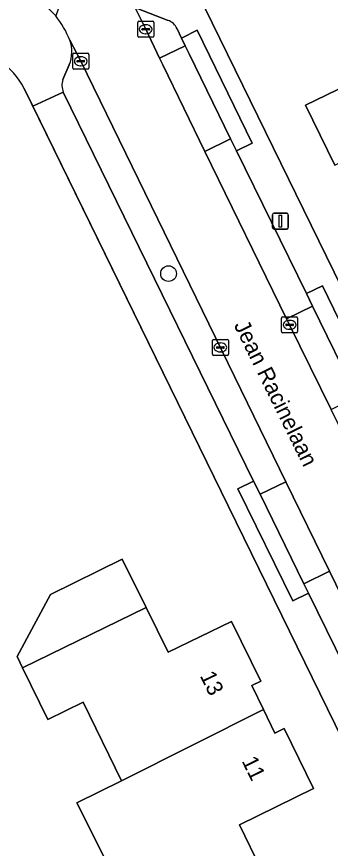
# Model space of a CAD drawing. Extents: x 160455 to 162082, y 388339 to 389736.
# Drawn here: x 160698.2 to 160717.8, y 388875.4 to 388927.4 of the extents above; entities that cross this region are included whole.
import ezdxf

# ---------------------------------------------------------------- set-up
doc = ezdxf.new("R2010")
doc.units = 0
for name, color, linetype in [('IMGEO_Boom', 7, 'Continuous'), ('IMGEO_Erf', 7, 'Continuous'), ('IMGEO_Kolk', 7, 'Continuous'), ('IMGEO_Lichtmast', 7, 'Continuous'), ('IMGEO_Muur', 7, 'Continuous'), ('IMGEO_Openbare_ruimte_label', 7, 'Continuous'), ('IMGEO_Pand', 7, 'Continuous'), ('IMGEO_Pand_nummerreeks', 7, 'Continuous'), ('IMGEO_Parkeervlak_open', 7, 'Continuous'), ('IMGEO_Rijbaan_lokaal_gesloten', 7, 'Continuous'), ('IMGEO_Rijbaan_lokaal_open', 7, 'Continuous'), ('IMGEO_Voetpad_open', 7, 'Continuous')]:
    doc.layers.add(name, color=color, linetype=linetype)

msp = doc.modelspace()

# ---------------------------------------------------------------- linework, layer by layer
at = {"layer": 'IMGEO_Boom'}
msp.add_circle((160707.652, 388911.311), 0.489, dxfattribs=at)
at = {"layer": 'IMGEO_Erf'}
for points in [[(160702.295, 388943.534), (160746.543, 388853.042), (160750.115, 388854.798), (160751.768, 388851.437), (160755.566, 388854.723), (160761.578, 388855.902), (160765.312, 388848.254), (160760.001, 388845.647), (160754.69, 388843.04), (160753.115, 388846.244), (160750.513, 388844.965), (160752.505, 388840.773)], [(160718.045, 388918.085), (160716.205, 388921.838), (160720.813, 388924.069)], [(160711.402, 388896.761), (160699.17, 388921.78), (160698.632, 388922.881)], [(160741.386, 388835.41), (160711.402, 388896.761)], [(160704.389, 388873.325), (160701.933, 388878.214), (160704.709, 388879.608), (160702.314, 388884.518), (160700.11, 388883.443), (160698.536, 388886.67), (160698.192, 388887.375), (160700.276, 388891.241), (160704.755, 388893.463), (160706.26, 388890.428), (160707.638, 388887.651), (160711.58, 388889.566), (160713.415, 388885.829), (160712.859, 388885.556), (160713.584, 388884.066), (160714.305, 388882.584), (160714.873, 388882.862), (160716.707, 388879.122), (160712.084, 388876.854), (160713.447, 388874.052)]]:
    msp.add_lwpolyline(points, dxfattribs=at)
msp.add_arc((160694.823, 388921.023), 4.238, 26.0033, 154.6119, dxfattribs=at)
at = {"layer": 'IMGEO_Kolk'}
for p, q in [((160705.728, 388926.167), (160705.728, 388927.019)), ((160705.803, 388927.093), (160706.655, 388927.093)), ((160706.216, 388926.873), (160706.241, 388926.873)), ((160706.729, 388927.019), (160706.729, 388926.167)), ((160705.987, 388926.587), (160705.987, 388926.599)), ((160706.425, 388926.55), (160706.027, 388926.55)), ((160706.03, 388926.636), (160706.428, 388926.636)), ((160706.239, 388926.313), (160706.214, 388926.313)), ((160706.471, 388926.599), (160706.471, 388926.587)), ((160706.655, 388926.093), (160705.803, 388926.093)), ((160701.669, 388924.168), (160701.669, 388925.02)), ((160701.744, 388925.094), (160702.596, 388925.094)), ((160701.971, 388924.637), (160702.369, 388924.637)), ((160702.157, 388924.874), (160702.182, 388924.874)), ((160702.67, 388925.02), (160702.67, 388924.168)), ((160701.928, 388924.588), (160701.928, 388924.6)), ((160702.366, 388924.551), (160701.968, 388924.551)), ((160702.18, 388924.314), (160702.155, 388924.314)), ((160702.412, 388924.6), (160702.412, 388924.588)), ((160702.596, 388924.094), (160701.744, 388924.094)), ((160714.72, 388907.685), (160714.72, 388908.537)), ((160714.795, 388908.611), (160715.647, 388908.611)), ((160715.721, 388908.537), (160715.721, 388907.685)), ((160714.979, 388908.105), (160714.979, 388908.117)), ((160715.417, 388908.068), (160715.019, 388908.068)), ((160715.022, 388908.154), (160715.42, 388908.154)), ((160715.208, 388908.391), (160715.233, 388908.391)), ((160715.463, 388908.117), (160715.463, 388908.105)), ((160715.647, 388907.611), (160714.795, 388907.611)), ((160715.231, 388907.831), (160715.206, 388907.831)), ((160710.393, 388906.269), (160710.393, 388907.121)), ((160710.468, 388907.195), (160711.32, 388907.195)), ((160710.881, 388906.975), (160710.906, 388906.975)), ((160711.394, 388907.121), (160711.394, 388906.269)), ((160710.652, 388906.689), (160710.652, 388906.701)), ((160711.09, 388906.652), (160710.692, 388906.652)), ((160710.695, 388906.738), (160711.093, 388906.738)), ((160711.136, 388906.701), (160711.136, 388906.689)), ((160711.32, 388906.195), (160710.468, 388906.195)), ((160710.904, 388906.415), (160710.879, 388906.415))]:
    msp.add_line(p, q, dxfattribs=at)
for points in [[(160705.728, 388926.167), (160705.728, 388927.019)], [(160705.803, 388927.093), (160706.655, 388927.093)], [(160706.729, 388927.019), (160706.729, 388926.167)], [(160706.655, 388926.093), (160705.803, 388926.093)], [(160701.669, 388924.168), (160701.669, 388925.02)], [(160701.744, 388925.094), (160702.596, 388925.094)], [(160702.67, 388925.02), (160702.67, 388924.168)], [(160702.596, 388924.094), (160701.744, 388924.094)], [(160714.72, 388907.685), (160714.72, 388908.537)], [(160714.795, 388908.611), (160715.647, 388908.611)], [(160715.721, 388908.537), (160715.721, 388907.685)], [(160715.647, 388907.611), (160714.795, 388907.611)], [(160710.393, 388906.269), (160710.393, 388907.121)], [(160710.468, 388907.195), (160711.32, 388907.195)], [(160711.394, 388907.121), (160711.394, 388906.269)], [(160711.32, 388906.195), (160710.468, 388906.195)]]:
    msp.add_lwpolyline(points, dxfattribs=at)
for centre, radius, start, end in [((160705.805, 388927.017), 0.0765, 91.552, 178.448), ((160705.805, 388927.017), 0.0765, 91.552, 178.448), ((160706.653, 388927.017), 0.0765, 1.552, 88.448), ((160706.653, 388927.017), 0.0765, 1.552, 88.448), ((160706.027, 388926.596), 0.0403, 85.8775, 175.7526), ((160706.024, 388926.586), 0.0366, 178.938, 274.7102), ((160706.428, 388926.593), 0.043, 264.8664, 352.4533), ((160706.432, 388926.598), 0.0386, 1.7309, 96.639), ((160705.805, 388926.169), 0.0765, 181.552, 268.448), ((160705.805, 388926.169), 0.0765, 181.552, 268.448), ((160706.653, 388926.169), 0.0765, 271.552, 358.448), ((160706.653, 388926.169), 0.0765, 271.552, 358.448), ((160701.746, 388925.018), 0.0765, 91.552, 178.448), ((160701.746, 388925.018), 0.0765, 91.552, 178.448), ((160701.968, 388924.597), 0.0403, 85.8775, 175.7526), ((160702.373, 388924.599), 0.0386, 1.7309, 96.639), ((160702.594, 388925.018), 0.0765, 1.552, 88.448), ((160702.594, 388925.018), 0.0765, 1.552, 88.448), ((160701.746, 388924.17), 0.0765, 181.552, 268.448), ((160701.746, 388924.17), 0.0765, 181.552, 268.448), ((160701.965, 388924.587), 0.0366, 178.938, 274.7102), ((160702.369, 388924.594), 0.043, 264.8664, 352.4533), ((160702.594, 388924.17), 0.0765, 271.552, 358.448), ((160702.594, 388924.17), 0.0765, 271.552, 358.448), ((160714.797, 388908.535), 0.0765, 91.552, 178.448), ((160714.797, 388908.535), 0.0765, 91.552, 178.448), ((160715.645, 388908.535), 0.0765, 1.552, 88.448), ((160715.645, 388908.535), 0.0765, 1.552, 88.448), ((160715.019, 388908.114), 0.0403, 85.8775, 175.7526), ((160715.016, 388908.104), 0.0366, 178.938, 274.7102), ((160715.42, 388908.111), 0.043, 264.8664, 352.4533), ((160715.424, 388908.116), 0.0386, 1.7309, 96.639), ((160714.797, 388907.687), 0.0765, 181.552, 268.448), ((160714.797, 388907.687), 0.0765, 181.552, 268.448), ((160715.645, 388907.687), 0.0765, 271.552, 358.448), ((160715.645, 388907.687), 0.0765, 271.552, 358.448), ((160710.47, 388907.119), 0.0765, 91.552, 178.448), ((160710.47, 388907.119), 0.0765, 91.552, 178.448), ((160711.318, 388907.119), 0.0765, 1.552, 88.448), ((160711.318, 388907.119), 0.0765, 1.552, 88.448), ((160710.692, 388906.698), 0.0403, 85.8775, 175.7526), ((160710.689, 388906.688), 0.0366, 178.938, 274.7102), ((160711.093, 388906.695), 0.043, 264.8664, 352.4533), ((160711.097, 388906.7), 0.0386, 1.7309, 96.639), ((160710.47, 388906.271), 0.0765, 181.552, 268.448), ((160710.47, 388906.271), 0.0765, 181.552, 268.448), ((160711.318, 388906.271), 0.0765, 271.552, 358.448), ((160711.318, 388906.271), 0.0765, 271.552, 358.448)]:
    msp.add_arc(centre, radius, start, end, dxfattribs=at)
for centre, major_axis, ratio, start_param, end_param in [((160706.215, 388926.593), (-0.387, 0.002), 0.722429, 4.712389, 7.853982), ((160706.24, 388926.593), (-0.39, 0.002), 0.717154, 1.570796, 4.712389), ((160702.156, 388924.594), (-0.387, 0.002), 0.722429, 4.712389, 7.853982), ((160702.181, 388924.594), (-0.39, 0.002), 0.717154, 1.570796, 4.712389), ((160715.207, 388908.111), (-0.387, 0.002), 0.722429, 4.712389, 7.853982), ((160715.232, 388908.111), (-0.39, 0.002), 0.717154, 1.570796, 4.712389), ((160710.88, 388906.695), (-0.387, 0.002), 0.722429, 4.712389, 7.853982), ((160710.905, 388906.695), (-0.39, 0.002), 0.717154, 1.570796, 4.712389)]:
    msp.add_ellipse(centre, major_axis=major_axis, ratio=ratio, start_param=start_param, end_param=end_param, dxfattribs=at)
at = {"layer": 'IMGEO_Lichtmast'}
for p, q in [((160714.148, 388914.196), (160714.148, 388914.996)), ((160714.148, 388914.996), (160714.148, 388914.196)), ((160714.248, 388915.096), (160715.038, 388915.096)), ((160715.038, 388915.096), (160714.248, 388915.096)), ((160715.138, 388914.996), (160715.138, 388914.196)), ((160715.138, 388914.196), (160715.138, 388914.996)), ((160715.038, 388914.096), (160714.248, 388914.096)), ((160714.248, 388914.096), (160715.038, 388914.096))]:
    msp.add_line(p, q, dxfattribs=at)
msp.add_lwpolyline([(160714.568, 388914.971), (160714.718, 388914.971), (160714.718, 388914.221), (160714.568, 388914.221), (160714.568, 388914.971)], dxfattribs=at)
for centre, start, end in [((160714.248, 388914.996), 90, 180), ((160714.248, 388914.996), 90, 180), ((160715.038, 388914.996), 0, 90), ((160715.038, 388914.996), 360, 90), ((160714.248, 388914.196), 180, 270), ((160714.248, 388914.196), 180, 270), ((160715.038, 388914.196), 270, 0), ((160715.038, 388914.196), 270, 0)]:
    msp.add_arc(centre, 0.1, start, end, dxfattribs=at)
at = {"layer": 'IMGEO_Muur'}
msp.add_lwpolyline([(160711.402, 388896.761), (160698.632, 388922.881)], dxfattribs=at)
msp.add_arc((160694.823, 388921.023), 4.238, 26.0033, 154.6119, dxfattribs=at)
at = {"layer": 'IMGEO_Pand'}
for points in [[(160726.489, 388930.328), (160719.442, 388926.87), (160720.813, 388924.069), (160716.205, 388921.838), (160718.045, 388918.085), (160718.61, 388918.362), (160719.343, 388916.864), (160728.231, 388921.239), (160730.401, 388922.33), (160728.012, 388927.214)], [(160706.26, 388890.428), (160704.755, 388893.463), (160700.276, 388891.241), (160698.192, 388887.375), (160698.536, 388886.67)], [(160706.26, 388890.428), (160698.536, 388886.67), (160700.11, 388883.443), (160702.314, 388884.518), (160704.709, 388879.608), (160713.584, 388884.066), (160712.859, 388885.556), (160713.415, 388885.829), (160711.58, 388889.566), (160707.638, 388887.651)], [(160706.442, 388870.511), (160713.447, 388874.052), (160712.084, 388876.854), (160716.707, 388879.122), (160714.873, 388882.862), (160714.305, 388882.584), (160713.584, 388884.066), (160704.709, 388879.608), (160701.933, 388878.214), (160704.389, 388873.325), (160704.935, 388873.599)]]:
    msp.add_lwpolyline(points, close=True, dxfattribs=at)
at = {"layer": 'IMGEO_Parkeervlak_open'}
for points in [[(160707.629, 388927.15), (160705.759, 388927.875), (160705.639, 388927.943), (160705.518, 388928.008), (160706.228, 388926.593), (160707.087, 388924.788), (160708.698, 388925.555), (160708.463, 388926.045), (160708.184, 388926.626)], [(160702.171, 388924.594), (160701.48, 388925.903)], [(160701.451, 388924.376), (160701.049, 388923.442)], [(160701.075, 388922.662), (160712.966, 388898.338), (160713.369, 388897.515), (160714.987, 388898.304), (160702.171, 388924.594)]]:
    msp.add_lwpolyline(points, dxfattribs=at)
for points in [[(160708.934, 388925.065), (160708.698, 388925.555), (160707.087, 388924.788), (160707.289, 388924.364), (160709.928, 388918.955), (160711.531, 388919.737)], [(160711.899, 388918.983), (160711.531, 388919.737), (160709.928, 388918.955), (160715.034, 388908.492), (160716.656, 388909.283), (160716.276, 388910.063)], [(160716.656, 388909.283), (160715.034, 388908.492), (160715.22, 388908.111), (160717.809, 388902.817), (160719.419, 388903.605)], [(160714.987, 388898.304), (160713.369, 388897.515), (160716.112, 388891.916), (160717.72, 388892.699)], [(160718.927, 388890.222), (160717.72, 388892.699), (160716.112, 388891.916), (160716.399, 388891.331), (160720.902, 388882.159), (160721.239, 388881.466), (160722.821, 388882.237)]]:
    msp.add_lwpolyline(points, close=True, dxfattribs=at)
for centre, radius, start, end in [((160707.269, 388926.213), 1.004, 24.3093, 68.9821), ((160699.563, 388925.176), 2.05, 337.0444, 20.7796), ((160702.164, 388923.089), 1.169, 162.4154, 201.4029)]:
    msp.add_arc(centre, radius, start, end, dxfattribs=at)
at = {"layer": 'IMGEO_Rijbaan_lokaal_gesloten'}
for points in [[(160725.78, 388886.522), (160722.954, 388892.3), (160717.809, 388902.817), (160715.22, 388908.111), (160715.034, 388908.492), (160709.928, 388918.955), (160707.289, 388924.364), (160707.087, 388924.788), (160706.228, 388926.593), (160705.518, 388928.008), (160705.103, 388928.339), (160704.831, 388928.646), (160703.057, 388931.096), (160702.245, 388932.077), (160700.602, 388927.427)], [(160701.48, 388925.903), (160702.171, 388924.594), (160714.987, 388898.304), (160717.72, 388892.699), (160718.927, 388890.222), (160722.821, 388882.237), (160725.648, 388876.442), (160727.942, 388871.738), (160730.503, 388866.526), (160733.518, 388860.392), (160735.965, 388855.414), (160738.64, 388849.931), (160741.656, 388843.751), (160743.781, 388839.396), (160745.065, 388836.754), (160745.48, 388835.906), (160749.558, 388837.942), (160749.315, 388838.459), (160747.718, 388841.637), (160740.066, 388857.393), (160733.637, 388870.475), (160732.064, 388873.676), (160730.834, 388876.19), (160725.78, 388886.522)]]:
    msp.add_lwpolyline(points, dxfattribs=at)
msp.add_arc((160696.15, 388923.847), 5.713, 21.0914, 38.8024, dxfattribs=at)
at = {"layer": 'IMGEO_Rijbaan_lokaal_open'}
msp.add_arc((160694.928, 388922.191), 7.721, 42.7017, 151.2116, dxfattribs=at)
at = {"layer": 'IMGEO_Voetpad_open'}
for points in [[(160750.513, 388844.965), (160746.543, 388853.042), (160702.295, 388943.534)], [(160699.647, 388935.048), (160700.848, 388934.173), (160700.533, 388933.771), (160702.245, 388932.077), (160703.057, 388931.096), (160704.831, 388928.646), (160705.103, 388928.339), (160705.518, 388928.008), (160705.639, 388927.943), (160705.759, 388927.875), (160707.629, 388927.15)], [(160708.184, 388926.626), (160708.463, 388926.045), (160709.452, 388926.526), (160712.888, 388919.464), (160711.899, 388918.983), (160716.276, 388910.063), (160717.265, 388910.544), (160720.83, 388903.219), (160719.841, 388902.738), (160724.214, 388893.81), (160725.202, 388894.294), (160728.78, 388886.987), (160727.792, 388886.503), (160732.174, 388877.574), (160732.623, 388877.793), (160736.06, 388870.759), (160735.611, 388870.54), (160749.695, 388841.654)], [(160701.049, 388923.442), (160701.451, 388924.376)], [(160698.632, 388922.881), (160699.17, 388921.78), (160701.075, 388922.662)], [(160701.075, 388922.662), (160699.17, 388921.78), (160711.402, 388896.761), (160741.386, 388835.41)], [(160742.283, 388838.406), (160740.552, 388841.994), (160739.565, 388841.509), (160735.596, 388849.58), (160736.583, 388850.065), (160732.122, 388859.249), (160731.135, 388858.763), (160727.688, 388865.759), (160728.675, 388866.245), (160724.301, 388875.158), (160723.311, 388874.678), (160719.912, 388881.679), (160720.902, 388882.159), (160716.399, 388891.331), (160715.411, 388890.847), (160711.978, 388897.854), (160712.966, 388898.338), (160701.075, 388922.662)]]:
    msp.add_lwpolyline(points, dxfattribs=at)
for points in [[(160709.452, 388926.526), (160708.463, 388926.045), (160708.698, 388925.555), (160708.934, 388925.065), (160711.531, 388919.737), (160711.899, 388918.983), (160712.888, 388919.464)], [(160717.265, 388910.544), (160716.276, 388910.063), (160716.656, 388909.283), (160719.419, 388903.605), (160719.841, 388902.738), (160720.83, 388903.219)], [(160713.369, 388897.515), (160712.966, 388898.338), (160711.978, 388897.854), (160715.411, 388890.847), (160716.399, 388891.331), (160716.112, 388891.916)]]:
    msp.add_lwpolyline(points, close=True, dxfattribs=at)
for centre, radius, start, end in [((160694.928, 388922.191), 7.721, 42.7017, 151.2116), ((160696.15, 388923.847), 5.713, 21.0914, 38.8024), ((160707.269, 388926.213), 1.004, 24.3093, 68.9821), ((160699.563, 388925.176), 2.05, 337.0444, 20.7796), ((160694.823, 388921.023), 4.238, 26.0033, 154.6119), ((160702.164, 388923.089), 1.169, 162.4154, 201.4029)]:
    msp.add_arc(centre, radius, start, end, dxfattribs=at)

# ---------------------------------------------------------------- texts
at = {"layer": 'IMGEO_Openbare_ruimte_label'}
msp.add_text('Jean Racinelaan', height=1, rotation=296.2319, dxfattribs=at).set_placement((160711.716, 388908.09))
at = {"layer": 'IMGEO_Pand_nummerreeks'}
for s, p in [('13', (160709.594, 388886.17)), ('11', (160712.207, 388880.845))]:
    msp.add_text(s, height=1, rotation=296.1466, dxfattribs=at).set_placement(p)

doc.saveas('drawing.dxf')
